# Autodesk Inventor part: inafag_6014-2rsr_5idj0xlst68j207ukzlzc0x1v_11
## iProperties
Shininess: 64.0
Angle Display Precision: 2
Document Length Units: 11269
Document Angle Units: 11279
Document Time Units: 11290
Document Mass Units: 11283
Document Length Units Precision: 3
Document Angle Units Precision: 2
Compacted: True
Created: 2008-08
Part Number: inafag_6014-2rsr_5idj0xlst68j207ukzlzc0x1v_11
Document SubType Name: Modeling
Designer: tpomodeler
Density: 0.0
Volumn: 0.0
Area: 0.0
PropertySet Name: Model Information
Control State: 0
Master: False
Checked Out: False
Author: tpomodeler
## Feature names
1. inafag_6014-2rsr_5idj0xlst68j207ukzlzc0x1v
